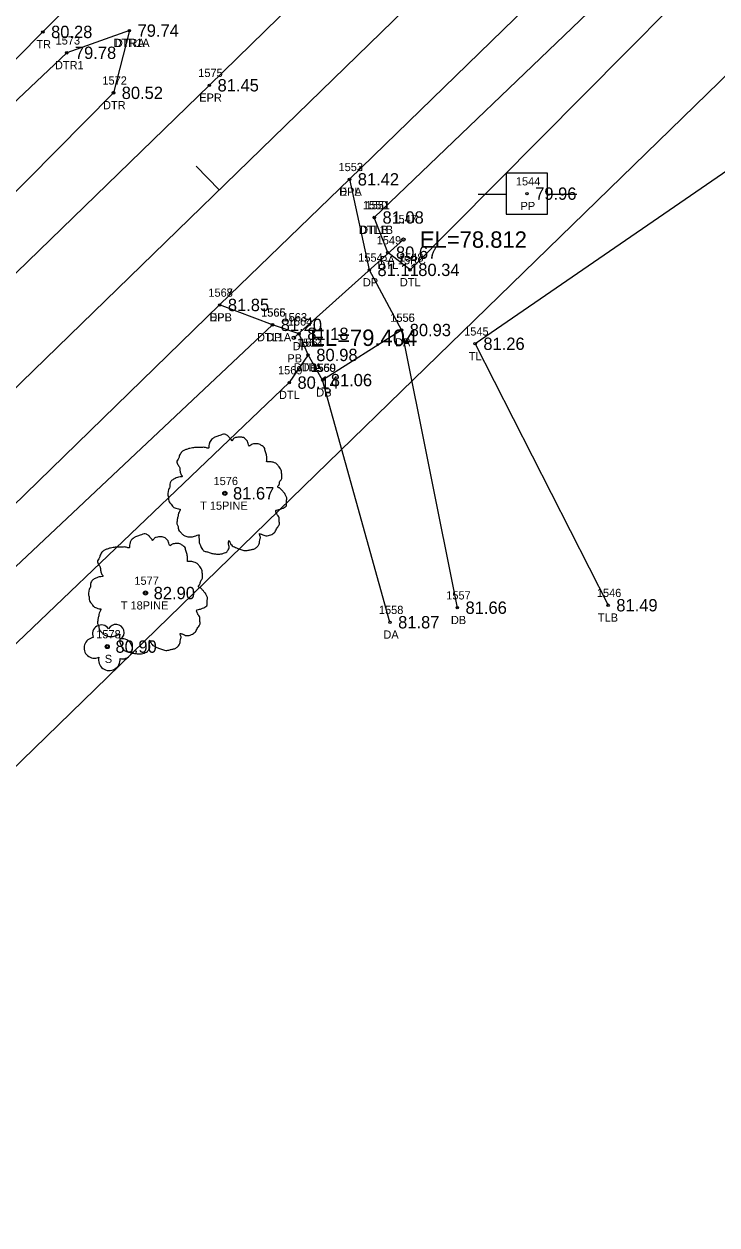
# Model space of a CAD drawing. Extents: x 2500794 to 2511032, y 910653 to 917533.
# Drawn here: x 2504933.5 to 2505017.8, y 912527.6 to 912673.7 of the extents above; entities that cross this region are included whole.
import ezdxf

# ---------------------------------------------------------------- set-up
doc = ezdxf.new("R2010")
doc.units = 0
for name, color, linetype in [('RD_EX_DR_Pipe', 7, 'Continuous'), ('RD_EX_DR_Pipe_txCode', 7, 'Continuous'), ('RD_EX_Driveway', 7, 'Continuous'), ('RD_EX_Driveway_txCode', 7, 'Continuous'), ('RD_EX_H2O_txCode', 7, 'Continuous'), ('RD_EX_Road', 7, 'Continuous'), ('RD_EX_Road_txCode', 7, 'Continuous'), ('RD_EX_RW', 7, 'Continuous'), ('RD_EX_TX_Driveway_ELEV', 7, 'Continuous'), ('RD_EX_TX_H2O_ELEV', 7, 'Continuous'), ('RD_EX_TX_Road_ELEV', 7, 'Continuous'), ('RD_EX_TX_VEG_ELEV', 7, 'Continuous'), ('RD_EX_UT', 7, 'Continuous'), ('RD_EX_UT_txCode', 7, 'Continuous'), ('RD_EX_VEG', 7, 'Continuous'), ('RD_EX_VEG_txCode', 7, 'Continuous'), ('RD_HC_Cl', 7, 'Continuous'), ('RD_HC_Data_Tic', 7, 'Continuous'), ('RD_HC_Survey_ELEV', 7, 'Continuous'), ('RD_SMD_Locator', 7, 'Continuous'), ('RD_TX_Pipe_ElevEX', 7, 'Continuous')]:
    doc.layers.add(name, color=color, linetype=linetype)

msp = doc.modelspace()

# ---------------------------------------------------------------- linework, layer by layer
at = {"layer": 'RD_EX_DR_Pipe'}
msp.add_line((2504979.68, 912647.44), (2504966.34, 912635.5), dxfattribs=at)
at = {"layer": 'RD_EX_Driveway'}
for p, q in [((2504979.44, 912636.44), (2504986.23, 912602.67)), ((2504978.03, 912600.9), (2504969.84, 912630.35))]:
    msp.add_line(p, q, dxfattribs=at)
msp.add_lwpolyline([(2504973.12, 912654.77), (2504975.52, 912643.75), (2504979.44, 912636.44), (2504969.84, 912630.35), (2504968.08, 912633.41), (2504966.98, 912635.98), (2504963.75, 912637.07), (2504957.32, 912639.49)], dxfattribs=at)
at = {"layer": 'RD_EX_H2O_txCode'}
msp.add_line((2505041.64, 912712.98), (2504976.13, 912650.13), dxfattribs=at)
for points in [[(2505042.85, 912708.63), (2505038.44, 912702.17), (2504980.48, 912643.76), (2504977.77, 912645.86), (2504976.13, 912650.13)], [(2504946.34, 912672.86), (2504944.41, 912665.29), (2504878.56, 912598.71), (2504823.61, 912548.12), (2504821.32, 912548.88), (2504819.92, 912553.07)], [(2504946.34, 912672.86), (2504938.72, 912670.16), (2504870.59, 912605.78), (2504819.92, 912553.07)], [(2504963.75, 912637.07), (2504900.54, 912577.61), (2504861.88, 912538.24), (2504863.18, 912534.99)], [(2504968.08, 912633.41), (2504965.79, 912630.05), (2504905.18, 912572.16), (2504865.9, 912533.66), (2504863.18, 912534.99)]]:
    msp.add_lwpolyline(points, dxfattribs=at)
at = {"layer": 'RD_EX_Road'}
for points in [[(2505356.25, 913055.37), (2505297.36, 912998.59), (2505254.44, 912956.44), (2505177.06, 912881.21), (2505102.21, 912808.73), (2505026.72, 912735.2), (2504956.07, 912666.21), (2504882.83, 912595.14), (2504825.46, 912547.52), (2504807.83, 912522.24), (2504732.55, 912448.69), (2504654.06, 912372.59), (2504585.1, 912305.45), (2504533.51, 912254.98)], [(2505370.6, 913041.78), (2505311.87, 912984.11), (2505268.01, 912941.43), (2505190.92, 912867.21), (2505116.28, 912794.43), (2505039.14, 912719.03), (2504973.12, 912654.77), (2504957.32, 912639.49), (2504897.44, 912581.22), (2504858.98, 912543.75), (2504838.29, 912523.7), (2504810.7, 912496.65), (2504795.8, 912482.32), (2504747.07, 912434.9), (2504696.6, 912386.17), (2504686.81, 912376.67), (2504668.39, 912358.37), (2504598.36, 912290.29), (2504547.08, 912240.34)]]:
    msp.add_lwpolyline(points, dxfattribs=at)
at = {"layer": 'RD_EX_RW'}
msp.add_line((2503981.18, 911658.03), (2505252.68, 912894.81), dxfattribs=at)
at = {"layer": 'RD_EX_UT'}
for p, q in [((2504997.19, 912655.53), (2504992.19, 912655.53)), ((2504992.19, 912655.53), (2504992.19, 912650.53)), ((2504997.19, 912650.53), (2504997.19, 912655.53)), ((2504988.76, 912652.97), (2504992.23, 912652.97)), ((2504997.12, 912652.97), (2505000.76, 912652.97)), ((2504992.19, 912650.53), (2504997.19, 912650.53))]:
    msp.add_line(p, q, dxfattribs=at)
at = {"layer": 'RD_EX_VEG'}
for points in [[(2505339.13, 913074.53), (2505242.44, 912974.3), (2505088.02, 912824.67), (2504935.82, 912672.7), (2504815.59, 912550.95), (2504817.4, 912591.81)], [(2505299.12, 912922.5), (2505143.93, 912762.37), (2505067.63, 912689.26), (2504988.4, 912634.77), (2505004.57, 912602.97)]]:
    msp.add_lwpolyline(points, dxfattribs=at)
for centre, radius in [((2504957.95, 912616.58), 0.25), ((2504957.93, 912616.56), 0.0001), ((2504948.3, 912604.45), 0.25), ((2504948.28, 912604.43), 0.0001), ((2504943.65, 912597.94), 0.25)]:
    msp.add_circle(centre, radius, dxfattribs=at)
for centre, radius, start, end in [((2504942.93, 912599.49), 1.08, 34.9763, 204.756), ((2504944.7, 912599.64), 0.995, 308.7626, 152.0467), ((2504942.09, 912597.78), 1.26, 96.4518, 294.734), ((2504945.49, 912597.66), 1.22, 256.5667, 98.1046), ((2504943.9, 912596.34), 1.32, 166.8827, 5.7589)]:
    msp.add_arc(centre, radius, start, end, dxfattribs=at)
for points in [[(2504958.08, 912623.75), (2504957.78, 912623.77), (2504957.45, 912623.67), (2504957.2, 912623.57), (2504956.98, 912623.5), (2504956.75, 912623.4), (2504956.45, 912623.22), (2504956.23, 912623.02), (2504956.1, 912622.77), (2504956.05, 912622.55), (2504956, 912622.27), (2504956, 912622.1), (2504955.88, 912622.07), (2504955.73, 912622.1), (2504955.48, 912622.17), (2504955.23, 912622.17), (2504954.98, 912622.17), (2504954.63, 912622.15), (2504954.28, 912622.15), (2504954, 912622.1), (2504953.68, 912622.05), (2504953.3, 912621.92), (2504952.95, 912621.8), (2504952.66, 912621.55), (2504952.41, 912621.08), (2504952.28, 912620.73), (2504952.13, 912620.48), (2504952.28, 912620.03), (2504952.46, 912619.68), (2504952.48, 912619.48), (2504952.56, 912619.05), (2504952.66, 912618.83), (2504952.78, 912618.63), (2504952.71, 912618.6), (2504952.33, 912618.55), (2504952.03, 912618.45), (2504951.61, 912618.23), (2504951.38, 912618), (2504951.28, 912617.68), (2504951.26, 912617.33), (2504951.16, 912617.13), (2504951.08, 912616.85), (2504951.06, 912616.78), (2504951.01, 912616.45), (2504951.11, 912616), (2504951.13, 912615.65), (2504951.26, 912615.43), (2504951.41, 912615.25), (2504951.58, 912615), (2504951.98, 912614.78), (2504952.31, 912614.68), (2504952.51, 912614.65), (2504952.33, 912614.15), (2504952.28, 912613.8), (2504952.16, 912613.4), (2504952.16, 912613.33), (2504952.11, 912612.85), (2504952.26, 912612.53), (2504952.33, 912612.15), (2504952.51, 912611.93), (2504952.78, 912611.63), (2504953.1, 912611.4), (2504953.6, 912611.28), (2504954, 912611.3), (2504954.58, 912611.48), (2504954.83, 912611.55), (2504954.8, 912611.38), (2504954.83, 912611), (2504954.83, 912610.58), (2504954.98, 912610.25), (2504955.08, 912609.98), (2504955.23, 912609.73), (2504955.55, 912609.51), (2504955.95, 912609.43), (2504956.38, 912609.28), (2504956.83, 912609.21), (2504957.33, 912609.18), (2504957.93, 912609.33), (2504958.2, 912609.46), (2504958.3, 912609.63), (2504958.5, 912610), (2504958.45, 912610.23), (2504958.48, 912610.83), (2504958.58, 912610.65), (2504958.75, 912610.3), (2504959.25, 912610), (2504959.65, 912609.83), (2504960.13, 912609.68), (2504960.43, 912609.61), (2504960.9, 912609.68), (2504961.28, 912609.76), (2504961.65, 912609.88), (2504961.95, 912610.15), (2504962.13, 912610.43), (2504962.18, 912610.7), (2504962.25, 912611.08), (2504962.3, 912611.25)], [(2504962.3, 912611.25), (2504962.23, 912611.43), (2504962.18, 912611.68), (2504962.25, 912611.65), (2504962.43, 912611.6), (2504962.7, 912611.48), (2504962.93, 912611.4), (2504963.25, 912611.43), (2504963.53, 912611.53), (2504963.98, 912611.8), (2504964.25, 912612.28), (2504964.52, 912612.68), (2504964.6, 912613), (2504964.55, 912613.23), (2504964.52, 912613.73), (2504964.32, 912613.98), (2504964.27, 912614.1), (2504964.17, 912614.5), (2504964.25, 912614.55), (2504964.52, 912614.6), (2504964.9, 912614.73), (2504965.17, 912614.85), (2504965.4, 912615.03), (2504965.47, 912615.25), (2504965.45, 912615.65), (2504965.5, 912616.05), (2504965.42, 912616.2), (2504965.32, 912616.35), (2504965.25, 912616.55), (2504965.1, 912616.7), (2504965, 912616.85), (2504964.9, 912616.95), (2504964.77, 912617.1), (2504964.6, 912617.23), (2504964.45, 912617.28), (2504964.4, 912617.43), (2504964.55, 912617.63), (2504964.6, 912617.73), (2504964.62, 912617.95), (2504964.85, 912618.3), (2504964.9, 912618.7), (2504964.85, 912619.13), (2504964.8, 912619.4), (2504964.65, 912619.68), (2504964.45, 912619.93), (2504964.32, 912620.1), (2504964.15, 912620.23), (2504963.83, 912620.35), (2504963.58, 912620.4), (2504963.23, 912620.4), (2504963.03, 912620.45), (2504963.05, 912620.5), (2504963.05, 912620.65), (2504963.05, 912620.93), (2504962.98, 912621.37), (2504962.83, 912621.87), (2504962.83, 912621.9), (2504962.73, 912622.15), (2504962.5, 912622.35), (2504962.33, 912622.45), (2504962.13, 912622.57), (2504961.88, 912622.6), (2504961.58, 912622.6), (2504961.3, 912622.55), (2504961.1, 912622.45), (2504960.93, 912622.32), (2504960.85, 912622.47), (2504960.75, 912622.77), (2504960.7, 912622.92), (2504960.55, 912623.1), (2504960.33, 912623.3), (2504959.88, 912623.42), (2504959.25, 912623.35), (2504958.95, 912623.15), (2504958.8, 912622.97), (2504958.75, 912623.1), (2504958.55, 912623.3), (2504958.45, 912623.47), (2504958.28, 912623.6), (2504958.13, 912623.7), (2504958.03, 912623.75)], [(2504948.43, 912611.62), (2504948.13, 912611.65), (2504947.8, 912611.55), (2504947.55, 912611.45), (2504947.33, 912611.37), (2504947.1, 912611.27), (2504946.8, 912611.1), (2504946.58, 912610.9), (2504946.45, 912610.65), (2504946.4, 912610.42), (2504946.35, 912610.15), (2504946.35, 912609.97), (2504946.23, 912609.95), (2504946.08, 912609.97), (2504945.83, 912610.05), (2504945.58, 912610.05), (2504945.33, 912610.05), (2504944.98, 912610.02), (2504944.63, 912610.02), (2504944.36, 912609.97), (2504944.03, 912609.92), (2504943.66, 912609.8), (2504943.31, 912609.67), (2504943.01, 912609.42), (2504942.76, 912608.95), (2504942.63, 912608.6), (2504942.48, 912608.35), (2504942.63, 912607.9), (2504942.81, 912607.55), (2504942.83, 912607.35), (2504942.91, 912606.92), (2504943.01, 912606.7), (2504943.13, 912606.5), (2504943.06, 912606.47), (2504942.68, 912606.42), (2504942.38, 912606.32), (2504941.96, 912606.1), (2504941.73, 912605.87), (2504941.63, 912605.55), (2504941.61, 912605.2), (2504941.51, 912605), (2504941.43, 912604.72), (2504941.41, 912604.65), (2504941.36, 912604.32), (2504941.46, 912603.87), (2504941.48, 912603.52), (2504941.61, 912603.3), (2504941.76, 912603.12), (2504941.93, 912602.87), (2504942.33, 912602.65), (2504942.66, 912602.55), (2504942.86, 912602.52), (2504942.68, 912602.02), (2504942.63, 912601.67), (2504942.51, 912601.27), (2504942.51, 912601.2), (2504942.46, 912600.73), (2504942.61, 912600.4), (2504942.68, 912600.03), (2504942.86, 912599.8), (2504943.13, 912599.5), (2504943.46, 912599.28), (2504943.96, 912599.15), (2504944.36, 912599.18), (2504944.93, 912599.35), (2504945.18, 912599.43), (2504945.15, 912599.25), (2504945.18, 912598.88), (2504945.18, 912598.45), (2504945.33, 912598.13), (2504945.43, 912597.85), (2504945.58, 912597.6), (2504945.9, 912597.38), (2504946.3, 912597.3), (2504946.73, 912597.15), (2504947.18, 912597.08), (2504947.68, 912597.05), (2504948.28, 912597.2), (2504948.55, 912597.33), (2504948.65, 912597.5), (2504948.85, 912597.88), (2504948.8, 912598.1), (2504948.83, 912598.7), (2504948.93, 912598.53), (2504949.1, 912598.18), (2504949.6, 912597.88), (2504950, 912597.7), (2504950.48, 912597.55), (2504950.78, 912597.48), (2504951.25, 912597.55), (2504951.63, 912597.63), (2504952, 912597.75), (2504952.3, 912598.03), (2504952.48, 912598.3), (2504952.53, 912598.58), (2504952.6, 912598.95), (2504952.65, 912599.13)], [(2504952.65, 912599.13), (2504952.58, 912599.3), (2504952.53, 912599.55), (2504952.6, 912599.53), (2504952.78, 912599.48), (2504953.05, 912599.35), (2504953.28, 912599.28), (2504953.6, 912599.3), (2504953.88, 912599.4), (2504954.33, 912599.68), (2504954.6, 912600.15), (2504954.88, 912600.55), (2504954.95, 912600.88), (2504954.9, 912601.1), (2504954.88, 912601.6), (2504954.68, 912601.85), (2504954.63, 912601.97), (2504954.53, 912602.37), (2504954.6, 912602.42), (2504954.88, 912602.47), (2504955.25, 912602.6), (2504955.53, 912602.72), (2504955.75, 912602.9), (2504955.82, 912603.12), (2504955.8, 912603.52), (2504955.85, 912603.92), (2504955.78, 912604.07), (2504955.68, 912604.22), (2504955.6, 912604.42), (2504955.45, 912604.57), (2504955.35, 912604.72), (2504955.25, 912604.82), (2504955.13, 912604.97), (2504954.95, 912605.1), (2504954.8, 912605.15), (2504954.75, 912605.3), (2504954.9, 912605.5), (2504954.95, 912605.6), (2504954.98, 912605.82), (2504955.2, 912606.17), (2504955.25, 912606.57), (2504955.2, 912607), (2504955.15, 912607.27), (2504955, 912607.55), (2504954.8, 912607.8), (2504954.68, 912607.97), (2504954.5, 912608.1), (2504954.18, 912608.22), (2504953.93, 912608.27), (2504953.58, 912608.27), (2504953.38, 912608.32), (2504953.4, 912608.37), (2504953.4, 912608.52), (2504953.4, 912608.8), (2504953.33, 912609.25), (2504953.18, 912609.75), (2504953.18, 912609.77), (2504953.08, 912610.02), (2504952.85, 912610.22), (2504952.68, 912610.32), (2504952.48, 912610.45), (2504952.23, 912610.47), (2504951.93, 912610.47), (2504951.65, 912610.42), (2504951.45, 912610.32), (2504951.28, 912610.2), (2504951.2, 912610.35), (2504951.1, 912610.65), (2504951.05, 912610.8), (2504950.9, 912610.97), (2504950.68, 912611.17), (2504950.23, 912611.3), (2504949.6, 912611.22), (2504949.3, 912611.02), (2504949.15, 912610.85), (2504949.1, 912610.97), (2504948.9, 912611.17), (2504948.8, 912611.35), (2504948.63, 912611.47), (2504948.48, 912611.57), (2504948.38, 912611.62)]]:
    msp.add_spline(points, degree=3, dxfattribs=at)
at = {"layer": 'RD_HC_Cl'}
msp.add_line((2504540.35, 912247.97), (2505598.79, 913277.5), dxfattribs=at)
at = {"layer": 'RD_HC_Data_Tic'}
msp.add_line((2504957.27, 912653.51), (2504954.48, 912656.37), dxfattribs=at)
at = {"layer": 'RD_SMD_Locator'}
for centre, radius in [((2504935.82, 912672.7), 0.15), ((2504946.34, 912672.86), 0.15), ((2504946.34, 912672.86), 0.15), ((2504938.72, 912670.16), 0.15), ((2504944.41, 912665.29), 0.15), ((2504956.07, 912666.21), 0.15), ((2504973.12, 912654.77), 0.15), ((2504973.12, 912654.77), 0.15), ((2504994.7, 912653.03), 0.15), ((2504976.13, 912650.13), 0.15), ((2504976.13, 912650.13), 0.15), ((2504979.68, 912647.44), 0.2), ((2504977.77, 912645.86), 0.15), ((2504975.52, 912643.75), 0.15), ((2504980.48, 912643.76), 0.15), ((2504957.32, 912639.49), 0.15), ((2504957.32, 912639.49), 0.15), ((2504963.75, 912637.07), 0.15), ((2504963.75, 912637.07), 0.15), ((2504966.98, 912635.98), 0.15), ((2504979.44, 912636.44), 0.15), ((2504979.44, 912636.44), 0.15), ((2504966.34, 912635.5), 0.2), ((2504988.4, 912634.77), 0.15), ((2504968.08, 912633.41), 0.15), ((2504968.08, 912633.41), 0.15), ((2504965.79, 912630.05), 0.15), ((2504969.84, 912630.35), 0.15), ((2504969.84, 912630.35), 0.15), ((2504957.95, 912616.58), 0.15), ((2504948.3, 912604.45), 0.15), ((2504986.23, 912602.67), 0.15), ((2505004.57, 912602.97), 0.15), ((2504978.03, 912600.9), 0.15), ((2504943.65, 912597.94), 0.15)]:
    msp.add_circle(centre, radius, dxfattribs=at)

# ---------------------------------------------------------------- texts
at = {"layer": 'RD_EX_DR_Pipe_txCode'}
for s, p in [('1547', (2504978.34, 912649.44)), ('PA 15RC', (2504976.84, 912644.44)), ('1563', (2504964.97, 912637.5)), ('PB', (2504965.56, 912632.5))]:
    msp.add_text(s, height=1, dxfattribs=at).set_placement(p)
at = {"layer": 'RD_EX_Driveway_txCode'}
for s, p in [('1553', (2504971.78, 912655.77)), ('DPA', (2504971.86, 912652.77)), ('1554', (2504974.18, 912644.75)), ('DP', (2504974.74, 912641.75)), ('1567', (2504955.95, 912640.49)), ('1565', (2504962.38, 912638.07)), ('DPB', (2504956.07, 912637.49)), ('1564', (2504965.61, 912636.98)), ('1556', (2504978.07, 912637.44)), ('1555', (2504978.09, 912637.44)), ('DP', (2504962.98, 912635.07)), ('DP', (2504966.2, 912633.98)), ('1561', (2504966.99, 912634.41)), ('DA', (2504978.65, 912634.44)), ('DP', (2504978.66, 912634.44)), ('DP', (2504967.3, 912631.41)), ('1560', (2504968.44, 912631.35)), ('1559', (2504968.5, 912631.35)), ('DB', (2504969.07, 912628.35)), ('DP', (2504969.07, 912628.35)), ('1557', (2504984.88, 912603.67)), ('1558', (2504976.69, 912601.9)), ('DB', (2504985.45, 912600.67)), ('DA', (2504977.24, 912598.9))]:
    msp.add_text(s, height=1, dxfattribs=at).set_placement(p)
at = {"layer": 'RD_EX_H2O_txCode'}
for s, p in [('1573', (2504937.37, 912671.16)), ('DTR1A', (2504944.42, 912670.86)), ('DTRA', (2504944.58, 912670.86)), ('DTR1', (2504937.29, 912668.16)), ('1572', (2504943.06, 912666.29)), ('DTR', (2504943.14, 912663.29)), ('1550', (2504974.75, 912651.13)), ('1551', (2504975.07, 912651.13)), ('DTL1B', (2504974.25, 912648.13)), ('DTLB', (2504974.41, 912648.13)), ('1549', (2504976.42, 912646.86)), ('DTL', (2504976.52, 912643.86)), ('1548', (2504979.14, 912644.76)), ('DTL', (2504979.24, 912641.76)), ('1566', (2504962.36, 912638.07)), ('DTL1A', (2504961.86, 912635.07)), ('1562', (2504966.71, 912634.41)), ('1569', (2504964.42, 912631.05)), ('DTLA', (2504966.35, 912631.41)), ('DTL', (2504964.54, 912628.05))]:
    msp.add_text(s, height=1, dxfattribs=at).set_placement(p)
at = {"layer": 'RD_EX_Road_txCode'}
for s, p in [('1575', (2504954.72, 912667.21)), ('EPR', (2504954.84, 912664.21)), ('1552', (2504971.78, 912655.77)), ('EPL', (2504971.92, 912652.77)), ('1568', (2504955.95, 912640.49)), ('EPL', (2504956.11, 912637.49))]:
    msp.add_text(s, height=1, dxfattribs=at).set_placement(p)
at = {"layer": 'RD_EX_TX_Driveway_ELEV'}
for s, p in [('81.42', (2504974.12, 912654.02)), ('81.11', (2504976.52, 912643)), ('81.85', (2504958.32, 912638.74)), ('81.20', (2504964.75, 912636.32)), ('80.93', (2504980.44, 912635.69)), ('80.93', (2504980.44, 912635.69)), ('81.18', (2504967.98, 912635.23)), ('80.98', (2504969.08, 912632.66)), ('81.06', (2504970.84, 912629.6)), ('81.06', (2504970.84, 912629.6)), ('81.66', (2504987.23, 912601.92)), ('81.87', (2504979.03, 912600.15))]:
    msp.add_text(s, height=1.5, dxfattribs=at).set_placement(p)
at = {"layer": 'RD_EX_TX_H2O_ELEV'}
for s, p in [('79.74', (2504947.34, 912672.11)), ('79.74', (2504947.34, 912672.11)), ('79.78', (2504939.72, 912669.41)), ('80.52', (2504945.41, 912664.54)), ('81.08', (2504977.13, 912649.38)), ('81.08', (2504977.13, 912649.38)), ('80.67', (2504978.77, 912645.11)), ('80.34', (2504981.48, 912643.01)), ('81.20', (2504964.75, 912636.32)), ('80.98', (2504969.08, 912632.66)), ('80.14', (2504966.79, 912629.3))]:
    msp.add_text(s, height=1.5, dxfattribs=at).set_placement(p)
at = {"layer": 'RD_EX_TX_Road_ELEV'}
for s, p in [('81.45', (2504957.07, 912665.46)), ('81.42', (2504974.12, 912654.02)), ('81.85', (2504958.32, 912638.74))]:
    msp.add_text(s, height=1.5, dxfattribs=at).set_placement(p)
at = {"layer": 'RD_EX_TX_VEG_ELEV'}
for s, p in [('80.28', (2504936.82, 912671.95)), ('81.26', (2504989.4, 912634.02)), ('81.67', (2504958.95, 912615.83)), ('82.90', (2504949.3, 912603.7)), ('81.49', (2505005.57, 912602.22)), ('80.90', (2504944.65, 912597.19))]:
    msp.add_text(s, height=1.5, dxfattribs=at).set_placement(p)
at = {"layer": 'RD_EX_UT_txCode'}
for s, p in [('1544', (2504993.35, 912654.03)), ('PP', (2504993.92, 912651.03))]:
    msp.add_text(s, height=1, dxfattribs=at).set_placement(p)
at = {"layer": 'RD_EX_VEG_txCode'}
for s, p in [('TR', (2504935.03, 912670.7)), ('1545', (2504987.06, 912635.77)), ('TL', (2504987.63, 912632.77)), ('1576', (2504956.58, 912617.58)), ('T 15PINE', (2504954.94, 912614.58)), ('1577', (2504946.95, 912605.45)), ('1546', (2505003.2, 912603.97)), ('T 18PINE', (2504945.29, 912602.45)), ('TLB', (2505003.33, 912600.97)), ('1578', (2504942.31, 912598.94)), ('S', (2504943.35, 912595.94))]:
    msp.add_text(s, height=1, dxfattribs=at).set_placement(p)
at = {"layer": 'RD_HC_Survey_ELEV'}
msp.add_text('79.96', height=1.5, dxfattribs=at).set_placement((2504995.7, 912652.28))
at = {"layer": 'RD_TX_Pipe_ElevEX'}
for s, p in [('EL=78.812', (2504981.68, 912646.44)), ('EL=79.404', (2504968.34, 912634.5))]:
    msp.add_text(s, height=2, dxfattribs=at).set_placement(p)

doc.saveas('drawing.dxf')
